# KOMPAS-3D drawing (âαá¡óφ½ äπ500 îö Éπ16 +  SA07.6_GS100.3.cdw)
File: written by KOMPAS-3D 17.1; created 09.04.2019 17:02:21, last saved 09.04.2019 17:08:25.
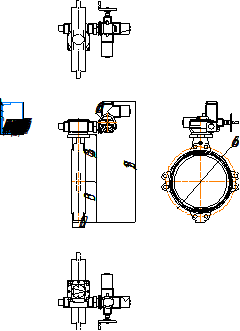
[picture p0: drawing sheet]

Sheet 1: A4, portrait

Title block, sheet 1: name: Гранвэл Ду500 МФ Ру16 + / SA07.6_GS100.3; material: Внимание! Данный продукт является объектом авторского права ООО «Торговый Дом АДЛ». / Запрещается изменение, копирование, распространение / (в том числе путем копирования на другие сайты и ресурсы в Интернете) / или любое иное использование информации и объектов без предварительного / согласия правообладателя (ООО «Торговый Дом АДЛ»).; mass: 266,41; sheets: 1; organisation: ООО "Торговый дом АДЛ"; sheet format: A4; stored path: \\adlc.lan\data\АДЛ_ПКД\3D-модели\ADL production\Дисковые поворотные затворы ГРАНВЭЛ\межфланцевый с эл.приводом Auma Ру 16\KOMPAS 2D\Гранвэл Ду500 МФ Ру16 +  SA07.6_GS100.3.cdw

Views: Вид 1, Проекционный вид 2, Проекционный вид 3, Проекционный вид 4
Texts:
  user
Dimensions and other numbers on the sheet: 432,5; 380; 105; 1125,3; 160; 650; 1:1; 1; 266,41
